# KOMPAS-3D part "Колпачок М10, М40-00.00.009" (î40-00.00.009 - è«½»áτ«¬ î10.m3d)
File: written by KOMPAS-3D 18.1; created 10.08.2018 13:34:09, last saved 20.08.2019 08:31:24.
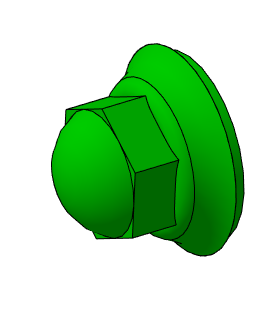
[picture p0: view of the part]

Document properties: Автор: Милов; Полное имя файла: D:\Magna\Магна Ins\Магна ins 40\3Д\М40-00.00.009 - Колпачок М10.m3d

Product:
- Part/product: Колпачок М10  | designation М40-00.00.009
    Масса: 0.0366477
    Раздел спецификации: Детали
    Форматы листов документа: A3
    source file: \\192.168.87.28\Konstructor_doc\Магна\Магна Ins\Магна ins 40\3Д\М40-00.00.009 - Колпачок М10.cdw
  - Component [standard]: Гайка М10-6H.21.12Х18Н10Т ГОСТ 11860-85  | Материал: Сталь 12Х18Н10Т ГОСТ 5632-72 (density 1000 kg/m3); Масса: 0.01746; Раздел спецификации: Стандартные изделия; source file: C:\Program Files\ASCON\KOMPAS-3D v18\Libs\PartLib\DATA\VAULT\methods\kompas\3d\PLib_Blind_Nut_type1_900.m3d
  - Body: Тело 1
      Масса: 0.0191877
- Part/product: Колпачок М10  | designation М40-00.00.009
    Масса: 0.0397944
  - Component [standard]: Гайка М10-6H.21.12Х18Н10Т ГОСТ 11860-85  | Материал: Сталь 12Х18Н10Т ГОСТ 5632-72 (density 1000 kg/m3); Масса: 0.01746; Раздел спецификации: Стандартные изделия; source file: C:\Program Files\ASCON\KOMPAS-3D v18\Libs\PartLib\DATA\VAULT\methods\kompas\3d\PLib_Blind_Nut_type1_900.m3d
  - Component [standard]: Шайба C.8.21 ГОСТ 11371-78  | Материал: Сталь 12Х18Н10Т ГОСТ 5632-72 (density 1000 kg/m3); Масса: 0.001725; Раздел спецификации: Стандартные изделия; source file: C:\Program Files\ASCON\KOMPAS-3D v18\Libs\PartLib\DATA\VAULT\methods\kompas\3d\PLib_Washer_1_712.m3d
  - Body: Тело 1
      Масса: 0.0206094

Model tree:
1. Эскиз:1
2. Операция вращения:1
     Угол 1 = 360
3. Смещенная плоскость:1  (with: Операция вращения:1)
     Расстояние = 8
4. Эскиз:2
5. Операция выдавливания:1
     Расстояние 2 = 18
6. Эскиз:3
7. Вырезать элемент вращения:2
     Угол 1 = 360
8. Эскиз:4  (with: Операция выдавливания:1)
9. Операция вращения:2
     Угол 1 = 360
10. Условное изображение резьбы:1  (labels: M10; cil0_24705-2004 coarse)
     Длина резьбы = 11; Шаг резьбы = 1.5; Номинальный диаметр резьбы = 10
11. Подгонка:1
12. Сечение поверхностью:3  (with: Операция вращения:1)  (labels: v241_v238_v9; v241_v238_v89)
     Расстояние = 17
13. Эскиз:5  (with: Операция вращения:1)
14. Вырезать элемент выдавливания:1
     Расстояние 1 = 2.5

Referenced files in C:\Program Files\ASCON\KOMPAS-3D v18\Libs\PartLib\DATA\VAULT\methods\kompas\3d\: PLib_Blind_Nut_type1_900.m3d, PLib_Washer_1_712.m3d
Referenced files in C:\Program Files\ASCON\KOMPAS-3D V16\Libs\PartLib\DATA\vault\Methods\Kompas\3D\: PLib_Blind_Nut_type1_900.m3d, PLib_Washer_1_712.m3d
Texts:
  foc1
  foc2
